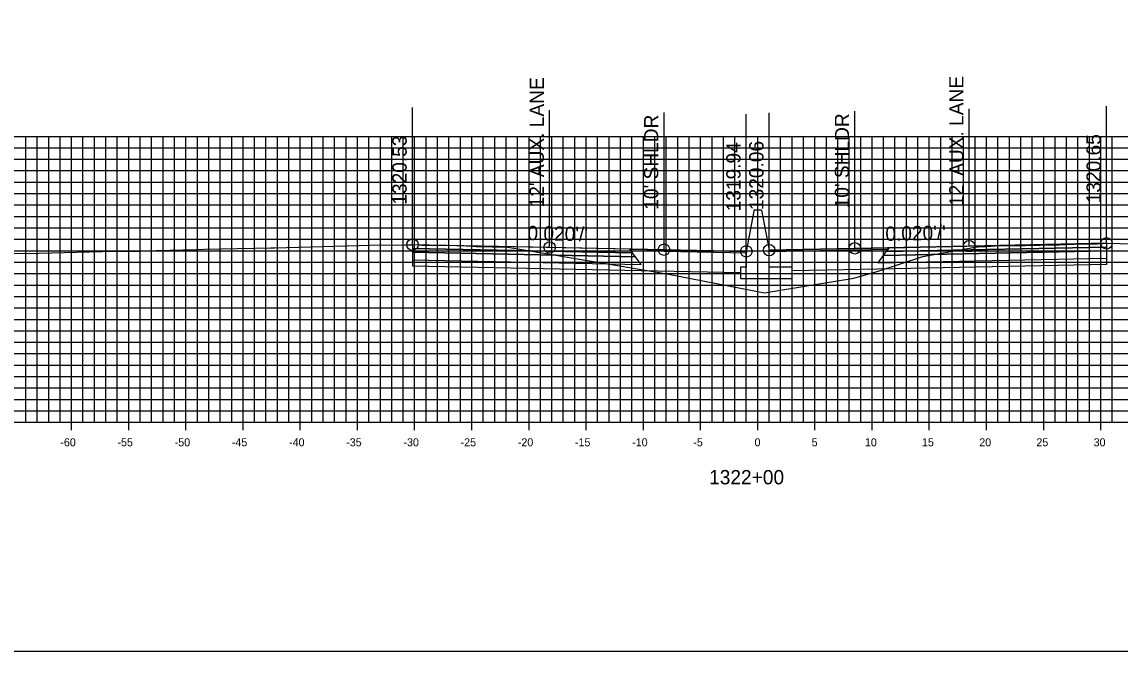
# Model space of a CAD drawing. Extents: x 674939 to 678919, y 750652 to 765176.
# Drawn here: x 678674.2 to 678770.2, y 751382.6 to 751437.6 of the extents above; entities that cross this region are included whole.
import ezdxf

# ---------------------------------------------------------------- set-up
doc = ezdxf.new("R2010")
doc.units = 0
for name, color, linetype in [('Level 10', 7, 'Continuous'), ('Level 17', 7, 'Continuous'), ('Level 18', 7, 'Continuous'), ('Level 19', 7, 'Continuous'), ('Level 20', 7, 'Continuous'), ('Level 22', 7, 'Continuous'), ('Level 23', 7, 'Continuous'), ('Level 4', 7, 'Continuous'), ('Level 8', 7, 'Continuous'), ('Level 9', 7, 'Continuous')]:
    doc.layers.add(name, color=color, linetype=linetype)

msp = doc.modelspace()

# ---------------------------------------------------------------- linework, layer by layer
at = {"layer": 'Level 10'}
msp.add_lwpolyline([(678673.495, 751417.316), (678674.279, 751417.325), (678674.821, 751417.316), (678675.664, 751417.336), (678682.304, 751417.503), (678682.488, 751417.504), (678684.463, 751417.523), (678684.507, 751417.525), (678684.668, 751417.529), (678684.768, 751417.534), (678689.457, 751417.669), (678690.168, 751417.686), (678695.92, 751417.806), (678696.284, 751417.815), (678703.66, 751418.002), (678704.605, 751418.024), (678707.664, 751418.073), (678707.929, 751418.077), (678708.336, 751418.079), (678708.351, 751418.079), (678708.485, 751418.08), (678709.204, 751418.047), (678709.304, 751418.042), (678709.484, 751418.041), (678712.185, 751417.998), (678712.325, 751417.996), (678713.045, 751417.972), (678713.084, 751417.981), (678713.104, 751417.989), (678713.379, 751417.967), (678713.401, 751417.967), (678713.913, 751417.93), (678716.679, 751417.855), (678725.755, 751416.348), (678729.568, 751415.714), (678730.579, 751415.531), (678739.113, 751413.867), (678740.886, 751414.151), (678746.936, 751415.141), (678749.05, 751415.771), (678752.963, 751417.032), (678756.224, 751417.641), (678757.702, 751417.901), (678757.819, 751417.905), (678757.866, 751417.907), (678758.196, 751417.896), (678759.683, 751418), (678760.066, 751418.016), (678760.561, 751418.007), (678760.736, 751418.004), (678761.396, 751417.988), (678761.727, 751418.003), (678761.901, 751418.01), (678762.892, 751418.023), (678762.996, 751418.023), (678763.24, 751418.027), (678764.892, 751418.076), (678765.379, 751418.093), (678767.031, 751418.156), (678767.693, 751418.14), (678767.866, 751418.137), (678768.693, 751418.19), (678768.831, 751418.201), (678768.859, 751418.201), (678769.023, 751418.197), (678770.208, 751418.174), (678775.997, 751418.055)], dxfattribs=at)
at = {"layer": 'Level 17'}
for points in [[(678738.203, 751420.995), (678737.533, 751417.495)], [(678738.863, 751421.107), (678738.863, 751421.107), (678738.203, 751421.107), (678738.203, 751420.995)], [(678738.863, 751421.107), (678739.533, 751417.607)], [(678737.533, 751417.495), (678737.533, 751416.12), (678737.033, 751416.12), (678737.033, 751415.12), (678741.533, 751415.12), (678741.533, 751416.12), (678739.533, 751416.12), (678739.533, 751417.607)]]:
    msp.add_lwpolyline(points, dxfattribs=at)
at = {"layer": 'Level 18'}
for points in [[(678737.533, 751417.495), (678730.336, 751417.639), (678720.336, 751417.839), (678708.336, 751418.079)], [(678769.023, 751418.197), (678757.023, 751417.957), (678747.023, 751417.757), (678739.533, 751417.607)]]:
    msp.add_lwpolyline(points, dxfattribs=at)
for points in [[(678708.336, 751418.079), (678708.336, 751417.749), (678727.586, 751417.364), (678727.336, 751417.699)], [(678727.336, 751417.699), (678737.533, 751417.495), (678737.537, 751417.337), (678727.455, 751417.539)], [(678749.904, 751417.658), (678739.533, 751417.45), (678739.533, 751417.607), (678750.023, 751417.817)], [(678769.023, 751418.197), (678769.023, 751417.867), (678749.773, 751417.482), (678750.023, 751417.817)]]:
    msp.add_lwpolyline(points, close=True, dxfattribs=at)
at = {"layer": 'Level 19'}
for points in [[(678708.336, 751417.749), (678708.336, 751417.419), (678727.836, 751417.029), (678727.586, 751417.364)], [(678769.023, 751417.867), (678769.023, 751417.537), (678749.523, 751417.147), (678749.773, 751417.482)], [(678708.336, 751417.419), (678708.336, 751416.759), (678728.336, 751416.359), (678727.836, 751417.029)], [(678769.023, 751417.537), (678769.023, 751416.877), (678749.023, 751416.477), (678749.523, 751417.147)]]:
    msp.add_lwpolyline(points, close=True, dxfattribs=at)
for points in [[(678708.336, 751416.759), (678708.336, 751416.219), (678728.336, 751415.819), (678737.033, 751415.645)], [(678769.023, 751416.877), (678769.023, 751416.337), (678749.023, 751415.937), (678741.533, 751415.787)]]:
    msp.add_lwpolyline(points, dxfattribs=at)
at = {"layer": 'Level 20'}
for p, q in [((678638.533, 751427.551), (678838.533, 751427.551)), ((678674.533, 751402.551), (678674.533, 751427.551)), ((678675.533, 751402.551), (678675.533, 751427.551)), ((678676.533, 751402.551), (678676.533, 751427.551)), ((678677.533, 751402.551), (678677.533, 751427.551)), ((678678.533, 751402.551), (678678.533, 751427.551)), ((678679.533, 751402.551), (678679.533, 751427.551)), ((678680.533, 751402.551), (678680.533, 751427.551)), ((678681.533, 751402.551), (678681.533, 751427.551)), ((678682.533, 751402.551), (678682.533, 751427.551)), ((678683.533, 751402.551), (678683.533, 751427.551)), ((678684.533, 751402.551), (678684.533, 751427.551)), ((678685.533, 751402.551), (678685.533, 751427.551)), ((678686.533, 751402.551), (678686.533, 751427.551)), ((678687.533, 751402.551), (678687.533, 751427.551)), ((678688.533, 751402.551), (678688.533, 751427.551)), ((678689.533, 751402.551), (678689.533, 751427.551)), ((678690.533, 751402.551), (678690.533, 751427.551)), ((678691.533, 751402.551), (678691.533, 751427.551)), ((678692.533, 751402.551), (678692.533, 751427.551)), ((678693.533, 751402.551), (678693.533, 751427.551)), ((678694.533, 751402.551), (678694.533, 751427.551)), ((678695.533, 751402.551), (678695.533, 751427.551)), ((678696.533, 751402.551), (678696.533, 751427.551)), ((678697.533, 751402.551), (678697.533, 751427.551)), ((678698.533, 751402.551), (678698.533, 751427.551)), ((678699.533, 751402.551), (678699.533, 751427.551)), ((678700.533, 751402.551), (678700.533, 751427.551)), ((678701.533, 751402.551), (678701.533, 751427.551)), ((678702.533, 751402.551), (678702.533, 751427.551)), ((678703.533, 751402.551), (678703.533, 751427.551)), ((678704.533, 751402.551), (678704.533, 751427.551)), ((678705.533, 751402.551), (678705.533, 751427.551)), ((678706.533, 751402.551), (678706.533, 751427.551)), ((678707.533, 751402.551), (678707.533, 751427.551)), ((678708.533, 751402.551), (678708.533, 751427.551)), ((678709.533, 751402.551), (678709.533, 751427.551)), ((678710.533, 751402.551), (678710.533, 751427.551)), ((678711.533, 751402.551), (678711.533, 751427.551)), ((678712.533, 751402.551), (678712.533, 751427.551)), ((678713.533, 751402.551), (678713.533, 751427.551)), ((678714.533, 751402.551), (678714.533, 751427.551)), ((678715.533, 751402.551), (678715.533, 751427.551)), ((678716.533, 751402.551), (678716.533, 751427.551)), ((678717.533, 751402.551), (678717.533, 751427.551)), ((678718.533, 751402.551), (678718.533, 751427.551)), ((678719.533, 751402.551), (678719.533, 751427.551)), ((678720.533, 751402.551), (678720.533, 751427.551)), ((678721.533, 751402.551), (678721.533, 751427.551)), ((678722.533, 751402.551), (678722.533, 751427.551)), ((678723.533, 751402.551), (678723.533, 751427.551)), ((678724.533, 751402.551), (678724.533, 751427.551)), ((678725.533, 751402.551), (678725.533, 751427.551)), ((678726.533, 751402.551), (678726.533, 751427.551)), ((678727.533, 751402.551), (678727.533, 751427.551)), ((678728.533, 751402.551), (678728.533, 751427.551)), ((678729.533, 751402.551), (678729.533, 751427.551)), ((678730.533, 751402.551), (678730.533, 751427.551)), ((678731.533, 751402.551), (678731.533, 751427.551)), ((678732.533, 751402.551), (678732.533, 751427.551)), ((678733.533, 751402.551), (678733.533, 751427.551)), ((678734.533, 751402.551), (678734.533, 751427.551)), ((678735.533, 751402.551), (678735.533, 751427.551)), ((678736.533, 751402.551), (678736.533, 751427.551)), ((678737.533, 751402.551), (678737.533, 751427.551)), ((678738.533, 751402.551), (678738.533, 751427.551)), ((678739.533, 751402.551), (678739.533, 751427.551)), ((678740.533, 751402.551), (678740.533, 751427.551)), ((678741.533, 751402.551), (678741.533, 751427.551)), ((678742.533, 751402.551), (678742.533, 751427.551)), ((678743.533, 751402.551), (678743.533, 751427.551)), ((678744.533, 751402.551), (678744.533, 751427.551)), ((678745.533, 751402.551), (678745.533, 751427.551)), ((678746.533, 751402.551), (678746.533, 751427.551)), ((678747.533, 751402.551), (678747.533, 751427.551)), ((678748.533, 751402.551), (678748.533, 751427.551)), ((678749.533, 751402.551), (678749.533, 751427.551)), ((678750.533, 751402.551), (678750.533, 751427.551)), ((678751.533, 751402.551), (678751.533, 751427.551)), ((678752.533, 751402.551), (678752.533, 751427.551)), ((678753.533, 751402.551), (678753.533, 751427.551)), ((678754.533, 751402.551), (678754.533, 751427.551)), ((678755.533, 751402.551), (678755.533, 751427.551)), ((678756.533, 751402.551), (678756.533, 751427.551)), ((678757.533, 751402.551), (678757.533, 751427.551)), ((678758.533, 751402.551), (678758.533, 751427.551)), ((678759.533, 751402.551), (678759.533, 751427.551)), ((678760.533, 751402.551), (678760.533, 751427.551)), ((678761.533, 751402.551), (678761.533, 751427.551)), ((678762.533, 751402.551), (678762.533, 751427.551)), ((678763.533, 751402.551), (678763.533, 751427.551)), ((678764.533, 751402.551), (678764.533, 751427.551)), ((678765.533, 751402.551), (678765.533, 751427.551)), ((678766.533, 751402.551), (678766.533, 751427.551)), ((678767.533, 751402.551), (678767.533, 751427.551)), ((678768.533, 751402.551), (678768.533, 751427.551)), ((678769.533, 751402.551), (678769.533, 751427.551)), ((678638.533, 751426.551), (678838.533, 751426.551)), ((678638.533, 751425.551), (678838.533, 751425.551)), ((678638.533, 751424.551), (678838.533, 751424.551)), ((678638.533, 751423.551), (678838.533, 751423.551)), ((678638.533, 751422.551), (678838.533, 751422.551)), ((678638.533, 751421.551), (678838.533, 751421.551)), ((678638.533, 751420.551), (678838.533, 751420.551)), ((678638.533, 751419.551), (678838.533, 751419.551)), ((678638.533, 751418.551), (678838.533, 751418.551)), ((678638.533, 751417.551), (678838.533, 751417.551)), ((678638.533, 751416.551), (678838.533, 751416.551)), ((678638.533, 751415.551), (678838.533, 751415.551)), ((678638.533, 751414.551), (678838.533, 751414.551)), ((678638.533, 751413.551), (678838.533, 751413.551)), ((678638.533, 751412.551), (678838.533, 751412.551)), ((678638.533, 751411.551), (678838.533, 751411.551)), ((678638.533, 751410.551), (678838.533, 751410.551)), ((678638.533, 751409.551), (678838.533, 751409.551)), ((678638.533, 751408.551), (678838.533, 751408.551)), ((678638.533, 751407.551), (678838.533, 751407.551)), ((678638.533, 751406.551), (678838.533, 751406.551)), ((678638.533, 751405.551), (678838.533, 751405.551)), ((678638.533, 751404.551), (678838.533, 751404.551)), ((678638.533, 751403.551), (678838.533, 751403.551)), ((678638.533, 751402.551), (678838.533, 751402.551))]:
    msp.add_line(p, q, dxfattribs=at)
at = {"layer": 'Level 23'}
for p, q in [((678708.336, 751418.079), (678708.336, 751430.079)), ((678769.023, 751418.197), (678769.023, 751430.197)), ((678720.336, 751417.839), (678720.336, 751429.839)), ((678730.336, 751417.639), (678730.336, 751429.639)), ((678737.533, 751417.495), (678737.533, 751429.495)), ((678739.533, 751417.607), (678739.533, 751429.607)), ((678747.023, 751417.757), (678747.023, 751429.757)), ((678757.023, 751417.957), (678757.023, 751429.957))]:
    msp.add_line(p, q, dxfattribs=at)
at = {"layer": 'Level 4'}
msp.add_lwpolyline([(678578.533, 751382.551), (678918.533, 751382.551), (678918.533, 751602.551), (678578.533, 751602.551)], close=True, dxfattribs=at)
for centre in [(678708.336, 751418.079), (678769.023, 751418.197), (678720.336, 751417.839), (678730.336, 751417.639), (678737.533, 751417.495), (678739.533, 751417.607), (678747.023, 751417.757), (678757.023, 751417.957)]:
    msp.add_circle(centre, 0.5, dxfattribs=at)
at = {"layer": 'Level 8'}
for p, q in [((678678.533, 751401.851), (678678.533, 751403.251)), ((678683.533, 751401.851), (678683.533, 751403.251)), ((678688.533, 751401.851), (678688.533, 751403.251)), ((678693.533, 751401.851), (678693.533, 751403.251)), ((678698.533, 751401.851), (678698.533, 751403.251)), ((678703.533, 751401.851), (678703.533, 751403.251)), ((678708.533, 751401.851), (678708.533, 751403.251)), ((678713.533, 751401.851), (678713.533, 751403.251)), ((678718.533, 751401.851), (678718.533, 751403.251)), ((678723.533, 751401.851), (678723.533, 751403.251)), ((678728.533, 751401.851), (678728.533, 751403.251)), ((678733.533, 751401.851), (678733.533, 751403.251)), ((678738.533, 751401.851), (678738.533, 751403.251)), ((678743.533, 751401.851), (678743.533, 751403.251)), ((678748.533, 751401.851), (678748.533, 751403.251)), ((678753.533, 751401.851), (678753.533, 751403.251)), ((678758.533, 751401.851), (678758.533, 751403.251)), ((678763.533, 751401.851), (678763.533, 751403.251)), ((678768.533, 751401.851), (678768.533, 751403.251)), ((678638.533, 751402.551), (678838.533, 751402.551))]:
    msp.add_line(p, q, dxfattribs=at)

# ---------------------------------------------------------------- texts
at = {"layer": 'Level 22'}
for rotation, p in [(358.85424, (678718.385, 751418.478)), (1.14576, (678749.704, 751418.411))]:
    msp.add_text("0.020'/'", height=1.25, rotation=rotation, dxfattribs=at).set_placement(p)
at = {"layer": 'Level 23'}
for s, p in [("12' AUX. LANE", (678719.836, 751421.339)), ("12' AUX. LANE", (678756.523, 751421.457)), ("10' SHLDR", (678729.836, 751421.139)), ("10' SHLDR", (678746.523, 751421.257)), ('1320.53', (678707.836, 751421.579)), ('1320.65', (678768.523, 751421.697)), ('1319.94', (678737.033, 751420.995)), ('1320.06', (678739.033, 751421.107))]:
    msp.add_text(s, height=1.25, rotation=90, dxfattribs=at).set_placement(p)
at = {"layer": 'Level 9'}
for s, height, p in [('-60', 0.7, (678677.552, 751400.451)), ('-55', 0.7, (678682.546, 751400.451)), ('-50', 0.7, (678687.552, 751400.451)), ('-45', 0.7, (678692.546, 751400.451)), ('-40', 0.7, (678697.552, 751400.451)), ('-35', 0.7, (678702.546, 751400.451)), ('-30', 0.7, (678707.552, 751400.451)), ('-25', 0.7, (678712.546, 751400.451)), ('-20', 0.7, (678717.552, 751400.451)), ('-15', 0.7, (678722.546, 751400.451)), ('-10', 0.7, (678727.552, 751400.451)), ('-5', 0.7, (678732.896, 751400.451)), ('0', 0.7, (678738.252, 751400.451)), ('5', 0.7, (678743.246, 751400.451)), ('10', 0.7, (678747.902, 751400.451)), ('15', 0.7, (678752.896, 751400.451)), ('20', 0.7, (678757.902, 751400.451)), ('25', 0.7, (678762.896, 751400.451)), ('30', 0.7, (678767.902, 751400.451)), ('1322+00', 1.25, (678734.281, 751397.126))]:
    msp.add_text(s, height=height, dxfattribs=at).set_placement(p)

doc.saveas('drawing.dxf')
